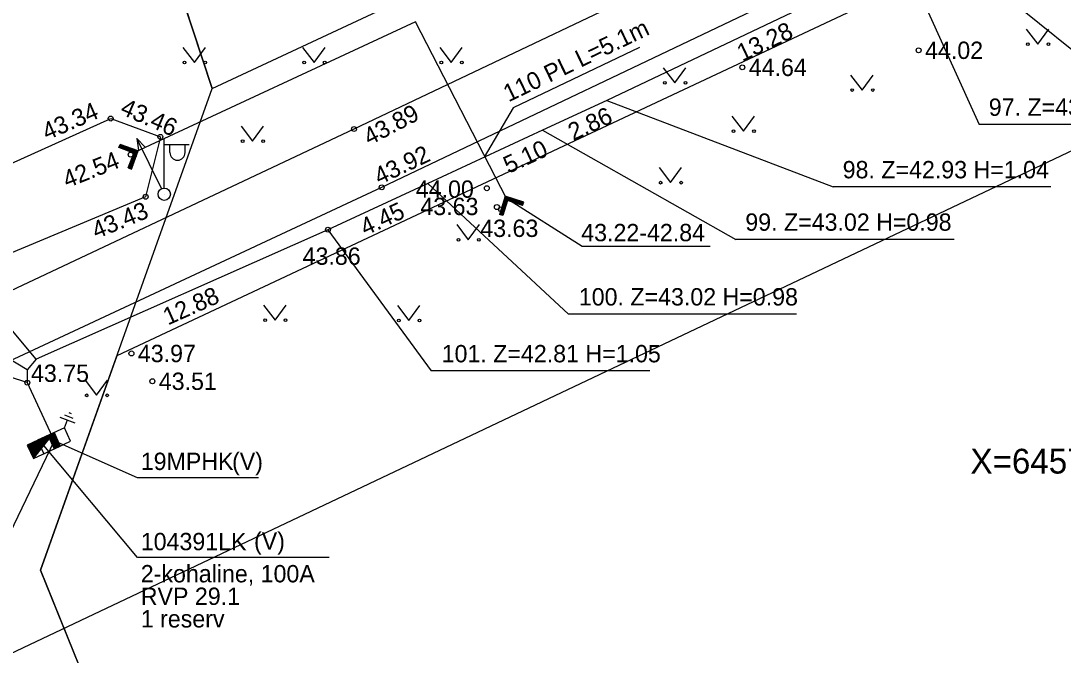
# Model space of a CAD drawing. Extents: x 642747 to 644424, y 6457048 to 6458238.
# Drawn here: x 643552.16 to 643594.24, y 6457442.17 to 6457467.77 of the extents above; entities that cross this region are included whole.
import ezdxf

# ---------------------------------------------------------------- set-up
doc = ezdxf.new("R2010")
doc.units = 0
for name, color, linetype in [('ABIJOONIS', 7, 'Continuous'), ('HALJASTUS', 7, 'Continuous'), ('JOONSIDE', 7, 'Continuous'), ('KOORDPUNKT', 7, 'Continuous'), ('KORGUS', 7, 'Continuous'), ('MOOTPIIR', 7, 'Continuous'), ('MPKAABEL', 7, 'Continuous'), ('MPOHULIIN', 7, 'Continuous'), ('PIIR', 7, 'Continuous'), ('POST', 7, 'Continuous'), ('TEE', 7, 'Continuous'), ('TRUUP', 7, 'Continuous'), ('VEEKOGU', 7, 'Continuous'), ('VORK', 7, 'Continuous')]:
    doc.layers.add(name, color=color, linetype=linetype)

msp = doc.modelspace()

# ---------------------------------------------------------------- linework, layer by layer
at = {"layer": 'ABIJOONIS'}
msp.add_lwpolyline([(643577.134, 6457466.693), (643572.04, 6457464.265), (643570.866, 6457462.263)], dxfattribs=at)
at = {"layer": 'HALJASTUS'}
for p, q in [((643592.755, 6457467.435), (643593.218, 6457466.828)), ((643593.218, 6457466.828), (643593.664, 6457467.435)), ((643558.708, 6457466.689), (643559.171, 6457466.083)), ((643559.171, 6457466.083), (643559.617, 6457466.689)), ((643563.538, 6457466.689), (643564.001, 6457466.083)), ((643564.001, 6457466.083), (643564.447, 6457466.689)), ((643569.077, 6457466.689), (643569.54, 6457466.083)), ((643569.54, 6457466.083), (643569.986, 6457466.689)), ((643578.101, 6457465.878), (643578.565, 6457465.272)), ((643578.565, 6457465.272), (643579.01, 6457465.878)), ((643585.663, 6457465.583), (643586.126, 6457464.977)), ((643586.126, 6457464.977), (643586.572, 6457465.583)), ((643580.87, 6457463.929), (643581.333, 6457463.322)), ((643581.333, 6457463.322), (643581.779, 6457463.929)), ((643561.054, 6457463.522), (643561.518, 6457462.916)), ((643561.518, 6457462.916), (643561.963, 6457463.522)), ((643577.93, 6457461.847), (643578.394, 6457461.24)), ((643578.394, 6457461.24), (643578.839, 6457461.847)), ((643569.765, 6457459.544), (643570.228, 6457458.937)), ((643570.228, 6457458.937), (643570.674, 6457459.544)), ((643561.961, 6457456.295), (643562.424, 6457455.688)), ((643562.424, 6457455.688), (643562.87, 6457456.295)), ((643567.365, 6457456.284), (643567.828, 6457455.677)), ((643567.828, 6457455.677), (643568.274, 6457456.284)), ((643554.757, 6457453.264), (643555.221, 6457452.658)), ((643555.221, 6457452.658), (643555.666, 6457453.264))]:
    msp.add_line(p, q, dxfattribs=at)
for centre in [(643592.817, 6457466.828), (643593.646, 6457466.828), (643558.77, 6457466.083), (643559.599, 6457466.083), (643563.6, 6457466.083), (643564.429, 6457466.083), (643569.139, 6457466.083), (643569.968, 6457466.083), (643578.164, 6457465.272), (643578.992, 6457465.272), (643585.725, 6457464.977), (643586.554, 6457464.977), (643580.932, 6457463.322), (643581.761, 6457463.322), (643561.117, 6457462.916), (643561.946, 6457462.916), (643577.993, 6457461.24), (643578.822, 6457461.24), (643569.827, 6457458.937), (643570.656, 6457458.937), (643562.023, 6457455.688), (643562.852, 6457455.688), (643567.427, 6457455.677), (643568.256, 6457455.677), (643554.82, 6457452.658), (643555.648, 6457452.658)]:
    msp.add_circle(centre, 0.055, dxfattribs=at)
at = {"layer": 'KOORDPUNKT'}
for p, q in [((643588.871, 6457471.215), (643594.598, 6457466.615)), ((643587.816, 6457470.26), (643590.855, 6457463.586)), ((643575.818, 6457464.557), (643584.957, 6457461.064)), ((643599.395, 6457463.586), (643590.855, 6457463.586)), ((643573.225, 6457463.356), (643581.026, 6457458.948)), ((643552.787, 6457454.11), (643545.938, 6457462.3)), ((643568.598, 6457461.211), (643574.269, 6457455.932)), ((643593.742, 6457461.064), (643584.957, 6457461.064)), ((643552.412, 6457453.688), (643542.56, 6457459.604)), ((643564.561, 6457459.341), (643568.732, 6457453.639)), ((643589.845, 6457458.948), (643581.026, 6457458.948)), ((643552.422, 6457453.169), (643540.042, 6457457.027)), ((643583.473, 6457455.932), (643574.269, 6457455.932)), ((643577.552, 6457453.639), (643568.732, 6457453.639)), ((643553.504, 6457450.823), (643550.197, 6457443.946))]:
    msp.add_line(p, q, dxfattribs=at)
for points in [[(643575.818, 6457464.557), (643575.818, 6457464.557), (643575.818, 6457464.557)], [(643573.225, 6457463.356), (643573.225, 6457463.356), (643573.225, 6457463.356)], [(643568.598, 6457461.211), (643568.598, 6457461.211), (643568.598, 6457461.211)], [(643564.561, 6457459.341), (643564.561, 6457459.341), (643564.561, 6457459.341)], [(643552.787, 6457454.11), (643552.787, 6457454.11), (643552.787, 6457454.11)], [(643552.412, 6457453.688), (643552.412, 6457453.688), (643552.412, 6457453.688)], [(643552.422, 6457453.169), (643552.422, 6457453.169), (643552.422, 6457453.169)], [(643553.504, 6457450.823), (643553.504, 6457450.823), (643553.504, 6457450.823)]]:
    msp.add_lwpolyline(points, dxfattribs=at)
at = {"layer": 'KORGUS'}
for centre in [(643588.408, 6457466.581), (643581.29, 6457465.892), (643555.789, 6457463.827), (643565.611, 6457463.403), (643557.795, 6457463.087), (643556.594, 6457462.37), (643566.731, 6457461.052), (643570.975, 6457461.015), (643557.201, 6457460.671), (643571.383, 6457460.254), (643571.55, 6457460.164), (643564.561, 6457459.341), (643556.626, 6457454.346), (643552.422, 6457453.169), (643557.472, 6457453.225)]:
    msp.add_circle(centre, 0.1, dxfattribs=at)
at = {"layer": 'MOOTPIIR'}
msp.add_lwpolyline([(643525.446, 6457467.559), (643537.447, 6457435.458), (643944.848, 6457628.51), (644046.626, 6457529.09), (644067.022, 6457529.09), (644138.408, 6457598.401), (644075.1, 6457775.215), (644046.02, 6457752.582), (644092.466, 6457611.94), (644070.657, 6457576.375), (644041.981, 6457570.717), (643942.223, 6457662.862)], close=True, dxfattribs=at)
at = {"layer": 'MPKAABEL'}
for points in [[(643609.518, 6457487.318), (643592.691, 6457479.179), (643588.311, 6457477.39), (643587.614, 6457476.732), (643587.444, 6457476.007), (643588.686, 6457473.068), (643588.871, 6457471.215), (643587.816, 6457470.26), (643575.818, 6457464.557), (643573.225, 6457463.356), (643568.598, 6457461.211), (643564.561, 6457459.341), (643552.787, 6457454.11), (643552.412, 6457453.688), (643552.422, 6457453.169), (643553.504, 6457450.823)], [(643573.225, 6457463.356), (643568.598, 6457461.211)], [(643553.742, 6457451.774), (643554.337, 6457451.551)], [(643553.92, 6457451.868), (643554.264, 6457451.738)], [(643554.098, 6457451.961), (643554.191, 6457451.926)], [(643553.92, 6457451.345), (643554.039, 6457451.663)]]:
    msp.add_lwpolyline(points, dxfattribs=at)
at = {"layer": 'MPOHULIIN'}
for p, q in [((643556.849, 6457463.017), (643556.913, 6457462.546)), ((643556.849, 6457463.017), (643557.182, 6457462.677)), ((643557.843, 6457460.999), (643556.849, 6457463.017))]:
    msp.add_line(p, q, dxfattribs=at)
at = {"layer": 'PIIR'}
for points in [[(643435.34, 6457542.04), (643098.5, 6457289.43), (643172.06, 6457253.87), (643223.42, 6457347.01), (643584.12, 6457368.52), (643583, 6457371.27), (643552.96, 6457445.6), (643559.88, 6457465.04), (643557.62, 6457471.91), (643549.02, 6457467.97), (643522.25, 6457534.76), (643503.06, 6457583.41)], [(643584.66, 6457564.95), (643522.25, 6457534.76), (643549.02, 6457467.97), (643557.62, 6457471.91), (643559.88, 6457465.04), (643621.69, 6457493.88), (643604.64, 6457517.47), (643625.03, 6457526.9), (643614.96, 6457547.58), (643595.54, 6457570.21)], [(643611.69, 6457480.38), (643556.04, 6457454.25), (643552.96, 6457445.6), (643583, 6457371.27), (643663.28, 6457376.5), (643653.77, 6457394.67), (643646.88, 6457409.03)]]:
    msp.add_lwpolyline(points, close=True, dxfattribs=at)
at = {"layer": 'POST'}
for p, q in [((643557.954, 6457461.024), (643557.954, 6457463.024)), ((643557.954, 6457462.774), (643558.954, 6457462.774)), ((643558.18, 6457462.453), (643558.18, 6457462.774)), ((643558.793, 6457462.453), (643558.793, 6457462.774)), ((643557.954, 6457460.774), (643557.954, 6457460.774)), ((643553.92, 6457451.345), (643552.837, 6457450.843)), ((643554.171, 6457450.803), (643553.92, 6457451.345)), ((643553.502, 6457451.151), (643552.418, 6457450.648)), ((643553.478, 6457451.121), (643552.425, 6457450.633)), ((643553.455, 6457451.092), (643552.432, 6457450.618)), ((643553.431, 6457451.062), (643552.439, 6457450.603)), ((643553.408, 6457451.033), (643552.446, 6457450.587)), ((643553.384, 6457451.003), (643552.453, 6457450.572)), ((643553.361, 6457450.974), (643552.46, 6457450.557)), ((643553.337, 6457450.944), (643552.467, 6457450.541)), ((643553.313, 6457450.915), (643552.475, 6457450.526)), ((643553.29, 6457450.885), (643552.482, 6457450.511)), ((643553.266, 6457450.856), (643552.489, 6457450.495)), ((643552.669, 6457450.107), (643553.502, 6457451.151)), ((643552.837, 6457450.843), (643553.088, 6457450.301)), ((643553.255, 6457451.037), (643553.506, 6457450.495)), ((643553.508, 6457451.137), (643553.262, 6457451.023)), ((643553.514, 6457451.124), (643553.268, 6457451.009)), ((643553.521, 6457451.11), (643553.274, 6457450.996)), ((643553.523, 6457451.104), (643553.277, 6457450.99)), ((643553.53, 6457451.09), (643553.283, 6457450.976)), ((643553.536, 6457451.077), (643553.29, 6457450.962)), ((643553.542, 6457451.063), (643553.296, 6457450.949)), ((643553.549, 6457451.049), (643553.302, 6457450.935)), ((643553.555, 6457451.036), (643553.309, 6457450.922)), ((643553.561, 6457451.022), (643553.315, 6457450.908)), ((643553.568, 6457451.009), (643553.321, 6457450.894)), ((643553.574, 6457450.995), (643553.328, 6457450.881)), ((643553.58, 6457450.981), (643553.334, 6457450.867)), ((643553.585, 6457450.971), (643553.339, 6457450.856)), ((643553.592, 6457450.957), (643553.345, 6457450.843)), ((643553.598, 6457450.943), (643553.352, 6457450.829)), ((643553.604, 6457450.93), (643553.358, 6457450.816)), ((643553.609, 6457450.919), (643553.363, 6457450.805)), ((643553.615, 6457450.905), (643553.369, 6457450.791)), ((643553.622, 6457450.892), (643553.375, 6457450.778)), ((643553.628, 6457450.878), (643553.382, 6457450.764)), ((643553.633, 6457450.867), (643553.387, 6457450.753)), ((643553.639, 6457450.854), (643553.393, 6457450.74)), ((643553.646, 6457450.84), (643553.399, 6457450.726)), ((643553.502, 6457451.151), (643553.753, 6457450.609)), ((643553.753, 6457450.609), (643553.502, 6457451.151)), ((643552.418, 6457450.648), (643552.669, 6457450.107)), ((643553.243, 6457450.826), (643552.496, 6457450.48)), ((643553.219, 6457450.797), (643552.503, 6457450.465)), ((643553.196, 6457450.768), (643552.51, 6457450.45)), ((643553.172, 6457450.738), (643552.517, 6457450.434)), ((643553.149, 6457450.709), (643552.524, 6457450.419)), ((643553.125, 6457450.679), (643552.531, 6457450.404)), ((643553.102, 6457450.65), (643552.538, 6457450.388)), ((643553.078, 6457450.62), (643552.545, 6457450.373)), ((643553.055, 6457450.591), (643552.553, 6457450.358)), ((643553.031, 6457450.561), (643552.56, 6457450.343)), ((643553.008, 6457450.532), (643552.567, 6457450.327)), ((643552.984, 6457450.502), (643552.574, 6457450.312)), ((643552.961, 6457450.473), (643552.581, 6457450.297)), ((643552.937, 6457450.443), (643552.588, 6457450.281)), ((643552.914, 6457450.414), (643552.595, 6457450.266)), ((643552.669, 6457450.107), (643553.753, 6457450.609)), ((643553.088, 6457450.301), (643554.171, 6457450.803)), ((643553.652, 6457450.827), (643553.406, 6457450.712)), ((643553.657, 6457450.816), (643553.411, 6457450.702)), ((643553.663, 6457450.802), (643553.417, 6457450.688)), ((643553.67, 6457450.789), (643553.423, 6457450.674)), ((643553.676, 6457450.775), (643553.43, 6457450.661)), ((643553.681, 6457450.764), (643553.435, 6457450.65)), ((643553.687, 6457450.751), (643553.441, 6457450.636)), ((643553.694, 6457450.737), (643553.447, 6457450.623)), ((643553.7, 6457450.723), (643553.454, 6457450.609)), ((643553.705, 6457450.713), (643553.459, 6457450.598)), ((643553.711, 6457450.699), (643553.465, 6457450.585)), ((643553.717, 6457450.685), (643553.471, 6457450.571)), ((643553.724, 6457450.672), (643553.477, 6457450.558)), ((643553.729, 6457450.661), (643553.482, 6457450.547)), ((643553.735, 6457450.647), (643553.489, 6457450.533)), ((643553.741, 6457450.634), (643553.495, 6457450.52)), ((643553.748, 6457450.62), (643553.501, 6457450.506)), ((643552.89, 6457450.384), (643552.602, 6457450.251)), ((643552.867, 6457450.355), (643552.609, 6457450.235)), ((643552.843, 6457450.325), (643552.616, 6457450.22)), ((643552.819, 6457450.296), (643552.623, 6457450.205)), ((643552.796, 6457450.266), (643552.631, 6457450.19)), ((643552.772, 6457450.237), (643552.638, 6457450.174)), ((643552.749, 6457450.207), (643552.645, 6457450.159)), ((643552.725, 6457450.178), (643552.652, 6457450.144)), ((643552.702, 6457450.148), (643552.659, 6457450.128)), ((643552.678, 6457450.119), (643552.666, 6457450.113))]:
    msp.add_line(p, q, dxfattribs=at)
for points in [[(643564.609, 6457446.119), (643556.873, 6457446.119), (643553.085, 6457450.629)], [(643561.751, 6457449.33), (643556.873, 6457449.33), (643553.504, 6457450.823)]]:
    msp.add_lwpolyline(points, dxfattribs=at)
msp.add_circle((643557.953, 6457460.772), 0.25, dxfattribs=at)
msp.add_arc((643558.487, 6457462.453), 0.306, 180, 0, dxfattribs=at)
at = {"layer": 'TEE'}
for points in [[(643600.86, 6457480.184), (643599.201, 6457479.452), (643582.041, 6457471.211), (643565.611, 6457463.403), (643548.923, 6457455.546), (643532.88, 6457449.019)], [(643533.975, 6457446.78), (643550.034, 6457453.271), (643566.731, 6457461.052), (643583.357, 6457468.986), (643599.987, 6457476.97), (643601.811, 6457477.818)]]:
    msp.add_lwpolyline(points, dxfattribs=at)
at = {"layer": 'TRUUP'}
for p, q in [((643556.12, 6457462.652), (643556.169, 6457462.785)), ((643556.718, 6457462.434), (643556.12, 6457462.652)), ((643556.125, 6457462.65), (643556.242, 6457462.759)), ((643556.135, 6457462.693), (643556.215, 6457462.769)), ((643556.809, 6457462.477), (643556.145, 6457462.719)), ((643556.152, 6457462.64), (643556.268, 6457462.749)), ((643556.154, 6457462.746), (643556.189, 6457462.778)), ((643556.9, 6457462.519), (643556.169, 6457462.785)), ((643556.178, 6457462.631), (643556.294, 6457462.74)), ((643556.204, 6457462.621), (643556.32, 6457462.73)), ((643556.231, 6457462.611), (643556.347, 6457462.721)), ((643556.257, 6457462.602), (643556.373, 6457462.711)), ((643556.283, 6457462.592), (643556.399, 6457462.701)), ((643556.309, 6457462.583), (643556.426, 6457462.692)), ((643556.336, 6457462.573), (643556.452, 6457462.682)), ((643556.362, 6457462.564), (643556.478, 6457462.673)), ((643556.388, 6457462.554), (643556.505, 6457462.663)), ((643556.415, 6457462.544), (643556.531, 6457462.654)), ((643556.441, 6457462.535), (643556.557, 6457462.644)), ((643556.467, 6457462.525), (643556.583, 6457462.634)), ((643556.494, 6457462.516), (643556.61, 6457462.625)), ((643556.52, 6457462.506), (643556.636, 6457462.615)), ((643556.5, 6457461.836), (643556.718, 6457462.434)), ((643556.546, 6457462.496), (643556.662, 6457462.606)), ((643556.556, 6457461.991), (643556.787, 6457462.208)), ((643556.567, 6457461.812), (643556.809, 6457462.477)), ((643556.573, 6457462.487), (643556.689, 6457462.596)), ((643556.575, 6457462.043), (643556.806, 6457462.26)), ((643556.594, 6457462.096), (643556.825, 6457462.312)), ((643556.599, 6457462.477), (643556.715, 6457462.586)), ((643556.613, 6457462.148), (643556.844, 6457462.365)), ((643556.625, 6457462.468), (643556.741, 6457462.577)), ((643556.632, 6457462.2), (643556.863, 6457462.417)), ((643556.634, 6457461.788), (643556.9, 6457462.519)), ((643556.651, 6457462.458), (643556.768, 6457462.567)), ((643556.651, 6457462.252), (643556.882, 6457462.469)), ((643556.67, 6457462.304), (643556.899, 6457462.519)), ((643556.678, 6457462.449), (643556.794, 6457462.558)), ((643556.689, 6457462.357), (643556.873, 6457462.529)), ((643556.704, 6457462.439), (643556.82, 6457462.548)), ((643556.708, 6457462.409), (643556.846, 6457462.539)), ((643556.5, 6457461.836), (643556.634, 6457461.788)), ((643556.501, 6457461.836), (643556.73, 6457462.051)), ((643556.518, 6457461.887), (643556.749, 6457462.104)), ((643556.527, 6457461.827), (643556.711, 6457461.999)), ((643556.537, 6457461.939), (643556.768, 6457462.156)), ((643556.554, 6457461.817), (643556.692, 6457461.947)), ((643556.58, 6457461.807), (643556.673, 6457461.895)), ((643556.606, 6457461.798), (643556.654, 6457461.843)), ((643571.722, 6457460.694), (643571.485, 6457459.952)), ((643571.768, 6457460.604), (643571.553, 6457459.931)), ((643571.814, 6457460.515), (643571.62, 6457459.909)), ((643571.784, 6457460.421), (643571.67, 6457460.533)), ((643571.793, 6457460.448), (643571.679, 6457460.559)), ((643571.801, 6457460.474), (643571.688, 6457460.586)), ((643571.81, 6457460.501), (643571.696, 6457460.613)), ((643571.84, 6457460.507), (643571.705, 6457460.639)), ((643571.893, 6457460.49), (643571.713, 6457460.666)), ((643572.463, 6457460.457), (643571.722, 6457460.694)), ((643571.946, 6457460.473), (643571.722, 6457460.693)), ((643572.442, 6457460.389), (643571.768, 6457460.604)), ((643571.998, 6457460.456), (643571.773, 6457460.677)), ((643572.42, 6457460.321), (643571.814, 6457460.515)), ((643572.051, 6457460.439), (643571.826, 6457460.661)), ((643572.104, 6457460.422), (643571.879, 6457460.644)), ((643572.157, 6457460.405), (643571.931, 6457460.627)), ((643572.21, 6457460.388), (643571.984, 6457460.61)), ((643572.263, 6457460.371), (643572.037, 6457460.593)), ((643572.316, 6457460.354), (643572.09, 6457460.576)), ((643572.369, 6457460.337), (643572.143, 6457460.559)), ((643572.42, 6457460.322), (643572.196, 6457460.542)), ((643572.429, 6457460.349), (643572.249, 6457460.525)), ((643572.437, 6457460.375), (643572.302, 6457460.508)), ((643571.648, 6457459.994), (643571.534, 6457460.106)), ((643571.656, 6457460.021), (643571.543, 6457460.133)), ((643571.665, 6457460.048), (643571.551, 6457460.159)), ((643571.673, 6457460.074), (643571.56, 6457460.186)), ((643571.682, 6457460.101), (643571.568, 6457460.213)), ((643571.69, 6457460.128), (643571.577, 6457460.239)), ((643571.699, 6457460.154), (643571.585, 6457460.266)), ((643571.707, 6457460.181), (643571.594, 6457460.293)), ((643571.716, 6457460.208), (643571.602, 6457460.319)), ((643571.724, 6457460.234), (643571.611, 6457460.346)), ((643571.733, 6457460.261), (643571.619, 6457460.373)), ((643571.742, 6457460.288), (643571.628, 6457460.399)), ((643571.75, 6457460.314), (643571.636, 6457460.426)), ((643571.759, 6457460.341), (643571.645, 6457460.453)), ((643571.767, 6457460.368), (643571.653, 6457460.479)), ((643571.776, 6457460.394), (643571.662, 6457460.506)), ((643572.446, 6457460.402), (643572.355, 6457460.491)), ((643572.454, 6457460.429), (643572.408, 6457460.474)), ((643572.42, 6457460.321), (643572.463, 6457460.457)), ((643571.62, 6457459.909), (643571.485, 6457459.952)), ((643571.525, 6457459.94), (643571.491, 6457459.973)), ((643571.578, 6457459.923), (643571.5, 6457459.999)), ((643571.622, 6457459.914), (643571.508, 6457460.026)), ((643571.631, 6457459.941), (643571.517, 6457460.053)), ((643571.639, 6457459.968), (643571.525, 6457460.079))]:
    msp.add_line(p, q, dxfattribs=at)
for points in [[(643571.768, 6457460.604), (643568.094, 6457467.735), (643556.809, 6457462.477)], [(643579.998, 6457458.669), (643574.821, 6457458.669), (643571.768, 6457460.604)]]:
    msp.add_lwpolyline(points, dxfattribs=at)
at = {"layer": 'VEEKOGU'}
for points in [[(643530.994, 6457452.88), (643535.943, 6457454.867), (643555.789, 6457463.827)], [(643555.789, 6457463.827), (643557.795, 6457463.087), (643557.201, 6457460.671), (643537.582, 6457452.477), (643532.247, 6457450.315)]]:
    msp.add_lwpolyline(points, dxfattribs=at)

# ---------------------------------------------------------------- texts
at = {"layer": 'ABIJOONIS'}
msp.add_text('110 PL L=5.1m', height=0.7, rotation=25.6556, dxfattribs=at).set_placement((643571.853, 6457464.479))
at = {"layer": 'JOONSIDE'}
for s, rotation, p in [('13.28', 25.4224, (643581.286, 6457466.115)), ('2.86', 24.8621, (643574.46, 6457462.923)), ('5.10', 24.8621, (643571.849, 6457461.59)), ('4.45', 24.8621, (643566.071, 6457459.084)), ('12.88', 23.9539, (643558.098, 6457455.473))]:
    msp.add_text(s, height=0.7, rotation=rotation, dxfattribs=at).set_placement(p)
at = {"layer": 'KOORDPUNKT'}
for s, p in [('97. Z=43.73 H=1.01', (643591.24, 6457463.936)), ('98. Z=42.93 H=1.04', (643585.342, 6457461.414)), ('99. Z=43.02 H=0.98', (643581.411, 6457459.298)), ('100. Z=43.02 H=0.98', (643574.689, 6457456.282)), ('101. Z=42.81 H=1.05', (643569.152, 6457453.989))]:
    msp.add_text(s, height=0.7, dxfattribs=at).set_placement(p)
at = {"layer": 'KORGUS'}
for s, p in [(' 44.02', (643588.408, 6457466.231)), (' 44.64', (643581.29, 6457465.542)), (' 44.00', (643567.848, 6457460.629)), (' 43.63', (643568.033, 6457459.93)), (' 43.63', (643570.452, 6457459.048)), ('43.86', (643563.538, 6457457.924)), (' 43.97', (643556.626, 6457453.996)), ('43.75', (643552.572, 6457453.199)), (' 43.51', (643557.472, 6457452.875))]:
    msp.add_text(s, height=0.7, dxfattribs=at).set_placement(p)
for s, rotation, p in [(' 43.34', 23.4896, (643552.975, 6457462.833)), (' 43.46', 336.5336, (643555.893, 6457464.13)), (' 43.89', 27.6268, (643566, 6457462.605)), (' 43.92', 25.4591, (643566.401, 6457461.024)), (' 42.54', 21.612, (643553.786, 6457460.913)), (' 43.43', 22.3919, (643554.969, 6457458.857))]:
    msp.add_text(s, height=0.7, rotation=rotation, dxfattribs=at).set_placement(p)
at = {"layer": 'POST'}
for s, p in [('19MPHK', (643557.004, 6457449.643)), ('(V)', (643560.689, 6457449.643)), ('104391LK', (643557.004, 6457446.406)), ('(V)', (643561.576, 6457446.432)), ('2-kohaline, 100A', (643557.004, 6457445.109)), ('RVP 29.1', (643557.004, 6457444.199)), ('1 reserv', (643557.004, 6457443.289))]:
    msp.add_text(s, height=0.7, dxfattribs=at).set_placement(p)
at = {"layer": 'TRUUP'}
msp.add_text('43.22-42.84', height=0.7, dxfattribs=at).set_placement((643574.787, 6457458.875))
at = {"layer": 'VORK'}
msp.add_text('X=6457450     ', height=1, dxfattribs=at).set_placement((643590.501, 6457449.5))

doc.saveas('drawing.dxf')
